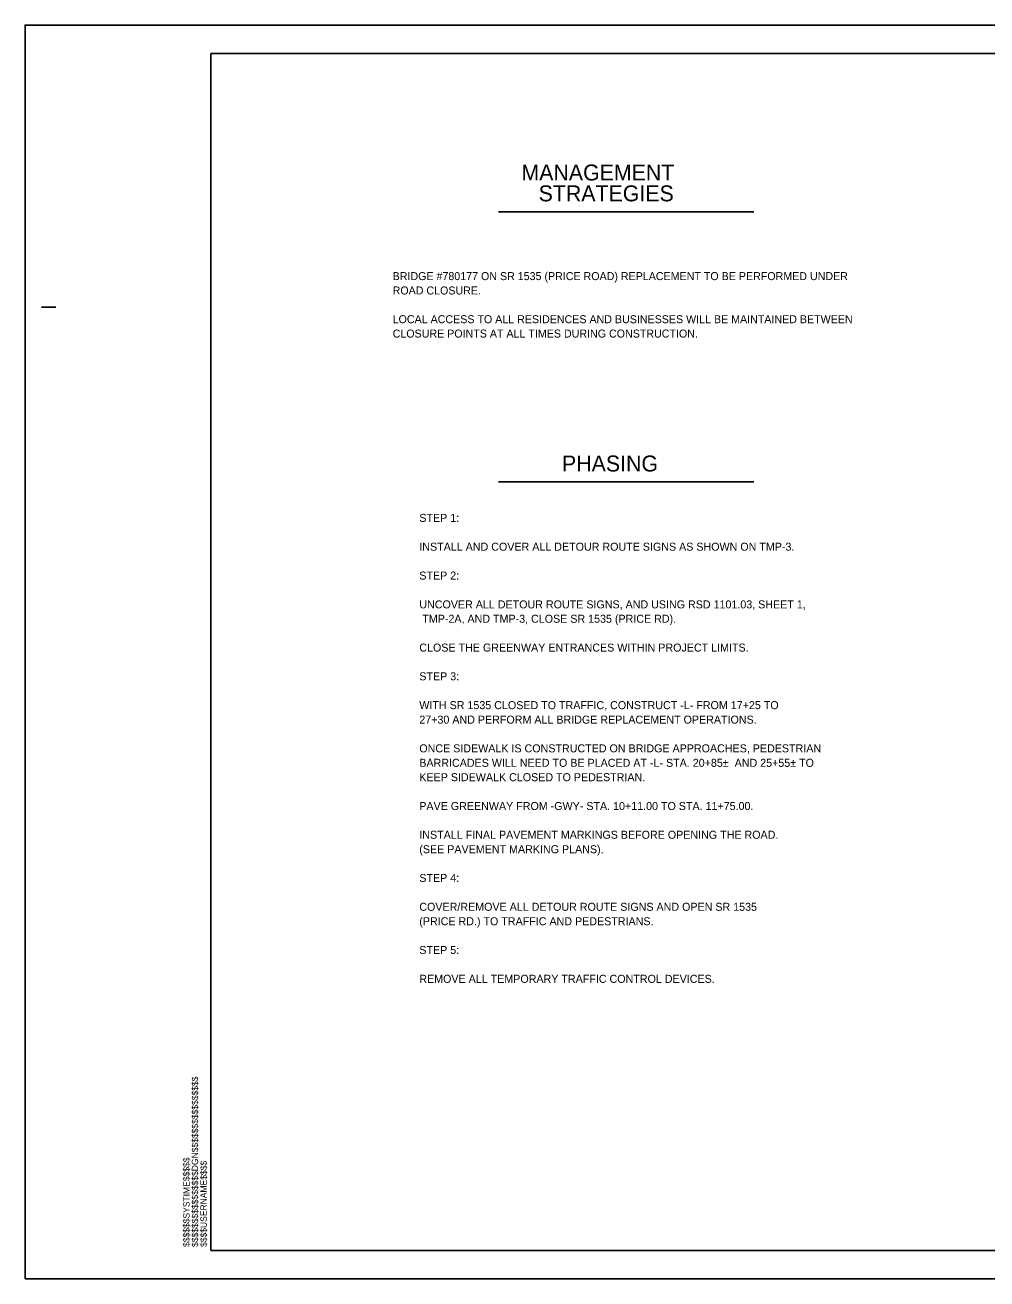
# Model space of a CAD drawing. Extents: x -38542 to 45858, y -25814 to 29186.
# Drawn here: x 168 to 1012, y -628 to 472 of the extents above; entities that cross this region are included whole.
import ezdxf

# ---------------------------------------------------------------- set-up
doc = ezdxf.new("R2010")
doc.units = 0
for name, color, linetype in [('DEV TYPE 3 BARRICADE WITH R11-2 M4-10R CELL', 7, 'Continuous'), ('Exist Road Non-System Type 51 Label', 7, 'Continuous'), ('Sheet Plot Border Outside CELL', 7, 'Continuous'), ('WZ RC1000 CELL', 7, 'Continuous')]:
    doc.layers.add(name, color=color, linetype=linetype)

msp = doc.modelspace()

# ---------------------------------------------------------------- linework, layer by layer
at = {"layer": 'Exist Road Non-System Type 51 Label'}
for p, q in [((332, 446.6), (332, 446.6)), ((182.5, 224.1), (195, 224.1)), ((331, -603.4), (331, -603.4))]:
    msp.add_line(p, q, dxfattribs=at)
msp.add_lwpolyline([(1831, 446.6), (331, 446.6), (331, -603.4), (1831, -603.4)], close=True, dxfattribs=at)
at = {"layer": 'Sheet Plot Border Outside CELL'}
msp.add_lwpolyline([(168, -628.4), (1856, -628.4), (1856, 471.6), (168, 471.6)], close=True, dxfattribs=at)
at = {"layer": 'WZ RC1000 CELL'}
for p, q in [((583.5, 307.8), (807.5, 307.8)), ((583.5, 70.8), (807.5, 70.8))]:
    msp.add_line(p, q, dxfattribs=at)

# ---------------------------------------------------------------- texts
at = {"layer": 'DEV TYPE 3 BARRICADE WITH R11-2 M4-10R CELL'}
for s, p in [('BRIDGE #780177 ON SR 1535 (PRICE ROAD) REPLACEMENT TO BE PERFORMED UNDER', (490.5, 247.9)), ('ROAD CLOSURE.', (490.5, 235.3)), ('LOCAL ACCESS TO ALL RESIDENCES AND BUSINESSES WILL BE MAINTAINED BETWEEN', (490.5, 210.1)), ('CLOSURE POINTS AT ALL TIMES DURING CONSTRUCTION.', (490.5, 197.5))]:
    msp.add_text(s, height=7, rotation=0, dxfattribs=at).set_placement(p)
for s, p in [('STEP 1:', (513.9, 35.8)), ('INSTALL AND COVER ALL DETOUR ROUTE SIGNS AS SHOWN ON TMP-3.', (513.9, 10.5)), ('STEP 2:', (513.9, -14.8)), ('UNCOVER ALL DETOUR ROUTE SIGNS, AND USING RSD 1101.03, SHEET 1,', (513.9, -40.1)), (' TMP-2A, AND TMP-3, CLOSE SR 1535 (PRICE RD).', (513.9, -52.7)), ('CLOSE THE GREENWAY ENTRANCES WITHIN PROJECT LIMITS. ', (513.9, -78)), ('STEP 3: ', (513.9, -103.2)), ('WITH SR 1535 CLOSED TO TRAFFIC, CONSTRUCT -L- FROM 17+25 TO', (513.9, -128.5)), ('27+30 AND PERFORM ALL BRIDGE REPLACEMENT OPERATIONS.', (513.9, -141.2)), ('ONCE SIDEWALK IS CONSTRUCTED ON BRIDGE APPROACHES, PEDESTRIAN', (513.9, -166.4)), ('BARRICADES WILL NEED TO BE PLACED AT -L- STA. 20+85±  AND 25+55± TO', (513.9, -179.1)), ('KEEP SIDEWALK CLOSED TO PEDESTRIAN. ', (513.9, -191.7)), ('PAVE GREENWAY FROM -GWY- STA. 10+11.00 TO STA. 11+75.00.', (513.9, -217)), ('INSTALL FINAL PAVEMENT MARKINGS BEFORE OPENING THE ROAD. ', (513.9, -242.2)), ('(SEE PAVEMENT MARKING PLANS).', (513.9, -254.9)), ('STEP 4:', (513.9, -280.1)), ('COVER/REMOVE ALL DETOUR ROUTE SIGNS AND OPEN SR 1535', (513.9, -305.4)), ('(PRICE RD.) TO TRAFFIC AND PEDESTRIANS.', (513.9, -318.1)), ('STEP 5:', (513.9, -343.3)), ('REMOVE ALL TEMPORARY TRAFFIC CONTROL DEVICES.', (513.9, -368.6))]:
    msp.add_text(s, height=7.02, dxfattribs=at).set_placement(p)
at = {"layer": 'Exist Road Non-System Type 51 Label'}
for s, p in [('MANAGEMENT ', (603.5, 335.3)), ('STRATEGIES', (618.6, 317)), ('PHASING', (639.1, 80))]:
    msp.add_text(s, height=14, dxfattribs=at).set_placement(p)
for s, p in [('$$$$$$$$$$$$$$$$DGN$$$$$$$$$$$$$$$$', (319.8, -600.3)), ('$$$$$$SYSTIME$$$$$', (312.3, -600.3)), ('$$$$USERNAME$$$$', (327.4, -600.3))]:
    msp.add_text(s, height=5.584, rotation=90, dxfattribs=at).set_placement(p)

doc.saveas('drawing.dxf')
